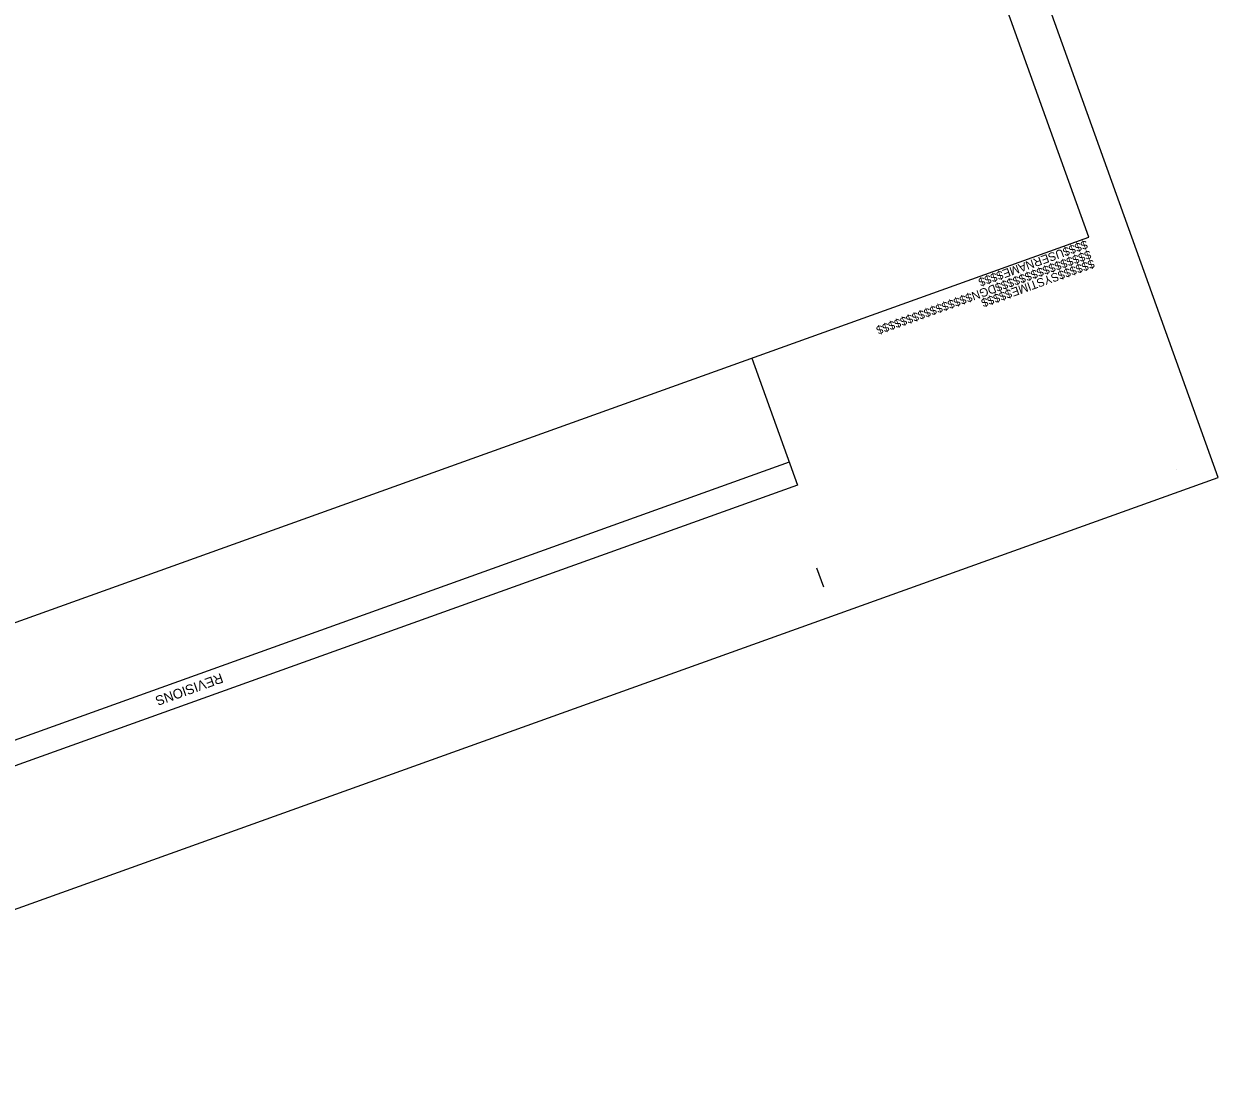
# Model space of a CAD drawing. Extents: x 480127 to 483680, y 514255 to 518588.
# Drawn here: x 482044 to 483680, y 514255 to 515699 of the extents above; entities that cross this region are included whole.
import ezdxf

# ---------------------------------------------------------------- set-up
doc = ezdxf.new("R2010")
doc.units = 0
for name, color, linetype in [('CTL Sheet Border CELL', 7, 'Continuous'), ('Sheet Block Revision CELL', 7, 'Continuous'), ('Sheet Plot Border Outside CELL', 7, 'Continuous')]:
    doc.layers.add(name, color=color, linetype=linetype)

msp = doc.modelspace()

# ---------------------------------------------------------------- linework, layer by layer
at = {"layer": 'CTL Sheet Border CELL'}
for p, q in [((483503, 515407.2), (483503, 515407.2)), ((483503, 515407.2), (483503, 515407.2)), ((483503, 515407.2), (483503, 515407.2)), ((483503, 515407.2), (483503, 515407.2)), ((483503, 515407.2), (483503, 515407.2)), ((483503, 515407.2), (483503, 515407.2)), ((483503, 515407.2), (483503, 515407.2)), ((483503, 515407.2), (483503, 515407.2)), ((483503, 515407.2), (483503, 515407.2)), ((483503, 515407.2), (483503, 515407.2)), ((483503, 515407.2), (483503, 515407.2)), ((483623.6, 515088.1), (483623.6, 515088.1)), ((483680.1, 515077.8), (483680.1, 515077.8)), ((483140, 514927.4), (483130.6, 514953.4))]:
    msp.add_line(p, q, dxfattribs=at)
msp.add_lwpolyline([(480191.8, 517748), (481314.5, 514621.4), (483503, 515407.2), (482380.4, 518533.8)], close=True, dxfattribs=at)
msp.add_lwpolyline([(483475, 515485.4), (483475, 515485.4)], dxfattribs=at)
msp.add_lwpolyline([(483475, 515485.4), (483475, 515485.4)], dxfattribs=at)
at = {"layer": 'Sheet Block Revision CELL'}
for p, q in [((483041.3, 515241.4), (483103.9, 515067.4)), ((483092.7, 515098.6), (481445.1, 514507)), ((483103.9, 515067.4), (481456.3, 514475.8))]:
    msp.add_line(p, q, dxfattribs=at)
at = {"layer": 'Sheet Plot Border Outside CELL'}
msp.add_lwpolyline([(483680.1, 515077.8), (482419.8, 518587.9), (480127, 517764.7), (481387.3, 514254.6)], close=True, dxfattribs=at)

# ---------------------------------------------------------------- texts
at = {"layer": 'CTL Sheet Border CELL'}
for s, p in [('$$$$USERNAME$$$$', (483498.9, 515403.2)), ('$$$$$$$$$$$$$$$$DGN$$$$$$$$$$$$$$$$', (483503.8, 515389.5)), ('$$$$$$SYSTIME$$$$$', (483508.4, 515376.9))]:
    msp.add_text(s, height=11.627, rotation=199.7508, dxfattribs=at).set_placement(p)
at = {"layer": 'Sheet Block Revision CELL'}
msp.add_text('REVISIONS', height=13.28, rotation=199.7508, dxfattribs=at).set_placement((482314.2, 514809.8))

doc.saveas('drawing.dxf')
